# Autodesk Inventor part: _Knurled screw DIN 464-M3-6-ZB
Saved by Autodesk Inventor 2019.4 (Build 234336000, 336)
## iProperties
Created: 2021-06
Part Number: _Knurled screw DIN 464-M3-6-ZB
Material: Generic
Document SubType Name: Modeling
Designer: Administrator
Density: 1 g/cm^3
Appearance: Default
Title: _Knurled screw DIN 464-M3-6-ZB
Author: Administrator
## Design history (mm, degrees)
feature "Body2"
body "Solid1"
